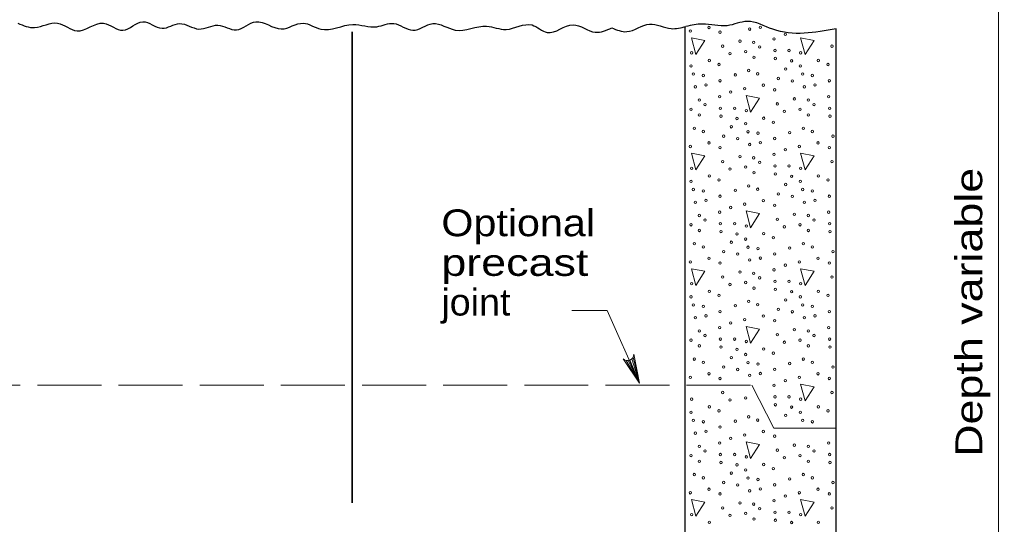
# Model space of a CAD drawing. Extents: x 1083.1 to 1117.1, y 697.4 to 719.4.
# Drawn here: x 1087.12 to 1092.81, y 707.6 to 710.54 of the extents above; entities that cross this region are included whole.
import ezdxf

# ---------------------------------------------------------------- set-up
doc = ezdxf.new("R2010")
doc.units = 0
doc.header["$LTSCALE"] = 0.062
doc.linetypes.add('LONG_DASHED', pattern=[7.5, 6, -1.5])
doc.layers.add('1', color=7, linetype='Continuous', lineweight=13)

msp = doc.modelspace()

# ---------------------------------------------------------------- linework, layer by layer
at = {"layer": '1'}
for p, q in [((1092.8115, 707.72683), (1092.8115, 711.52217)), ((1091.73883, 710.417), (1091.66092, 710.43225)), ((1090.68642, 708.574), (1090.72433, 708.42275)), ((1090.64575, 708.555), (1090.72433, 708.42275)), ((1090.65742, 708.55425), (1090.72433, 708.42275)), ((1090.668, 708.557), (1090.72433, 708.42275)), ((1090.67958, 708.56475), (1090.72433, 708.42275)), ((1092.8115, 701.31858), (1092.8115, 707.72683))]:
    msp.add_line(p, q, dxfattribs=at)
at = {"layer": '1', "lineweight": 35}
msp.add_line((1089.05217, 710.46625), (1089.05217, 707.72733), dxfattribs=at)
at = {"layer": '1', "lineweight": 25}
for p, q in [((1090.98767, 710.498), (1090.98767, 706.54908)), ((1091.86725, 706.529), (1091.86725, 710.48442))]:
    msp.add_line(p, q, dxfattribs=at)
at = {"layer": '1', "linetype": 'LONG_DASHED'}
for p, q in [((1086.75008, 708.41083), (1091.37633, 708.41083)), ((1091.37633, 708.41083), (1091.50542, 708.16167)), ((1091.50542, 708.16167), (1091.86567, 708.16167))]:
    msp.add_line(p, q, dxfattribs=at)
at = {"layer": '1'}
for points in [[(1091.02658, 710.43225), (1091.05217, 710.33483), (1091.10442, 710.417)], [(1091.34375, 710.09633), (1091.36942, 709.99908), (1091.42158, 710.08125)], [(1091.02658, 709.76058), (1091.05217, 709.66325), (1091.10442, 709.74542)], [(1091.66092, 709.76058), (1091.68658, 709.66325), (1091.73883, 709.74542)], [(1091.34375, 709.42475), (1091.36942, 709.32742), (1091.42158, 709.4095)], [(1091.02658, 709.08892), (1091.05217, 708.99158), (1091.10442, 709.07375)], [(1091.66092, 709.08892), (1091.68658, 708.99158), (1091.73883, 709.07375)], [(1091.34375, 708.75308), (1091.36942, 708.65575), (1091.42158, 708.73792)], [(1091.66092, 708.41725), (1091.68658, 708.31992), (1091.73883, 708.40208)], [(1091.34375, 708.08142), (1091.36942, 707.98408), (1091.42158, 708.06625)], [(1091.02658, 707.74567), (1091.05217, 707.64825), (1091.10442, 707.73042)], [(1091.66092, 707.74567), (1091.68658, 707.64825), (1091.73883, 707.73042)]]:
    msp.add_lwpolyline(points, close=True, dxfattribs=at)
for points in [[(1091.66092, 710.43225), (1091.68658, 710.33483), (1091.73883, 710.417)], [(1090.72433, 708.42275), (1090.53533, 708.84483), (1090.3305, 708.84483)], [(1090.69025, 708.59092), (1090.72433, 708.42275), (1090.62817, 708.56492)]]:
    msp.add_lwpolyline(points, dxfattribs=at)
msp.add_arc((1090.65393, 708.59041), 0.03631, 224.86313, 0.68926, dxfattribs=at)
for centre in [(1091.01889, 710.47171), (1091.12764, 710.49259), (1091.19277, 710.46539), (1091.36517, 710.48291), (1091.42686, 710.49382), (1091.57188, 710.45268), (1091.30754, 710.41283), (1091.38837, 710.40584), (1091.50685, 710.42548), (1091.02745, 710.34477), (1091.2082, 710.38378), (1091.24934, 710.34024), (1091.34095, 710.35205), (1091.42205, 710.37925), (1091.51198, 710.35837), (1091.59424, 710.35837), (1091.66186, 710.34477), (1091.84261, 710.38378), (1091.12938, 710.30033), (1091.18589, 710.27677), (1091.38922, 710.31908), (1091.51452, 710.31214), (1091.60793, 710.29854), (1091.76378, 710.30033), (1091.8203, 710.27677), (1091.02402, 710.2686), (1091.03776, 710.22147), (1091.28042, 710.21666), (1091.35925, 710.24201), (1091.41148, 710.22298), (1091.57447, 710.25046), (1091.65842, 710.2686), (1091.67216, 710.22147), (1091.09512, 710.21324), (1091.19277, 710.1824), (1091.53138, 710.19578), (1091.61216, 710.18156), (1091.72952, 710.21324), (1091.82717, 710.1824), (1091.04797, 710.14708), (1091.10966, 710.158), (1091.25467, 710.11686), (1091.33609, 710.13589), (1091.44484, 710.15677), (1091.50997, 710.12957), (1091.68237, 710.14708), (1091.74406, 710.158), (1091.07117, 710.07001), (1091.18965, 710.08966), (1091.52541, 710.04796), (1091.62474, 710.07701), (1091.70558, 710.07001), (1091.82405, 710.08966), (1091.02375, 710.01622), (1091.10485, 710.04343), (1091.19478, 710.02255), (1091.27704, 710.02255), (1091.34465, 710.00895), (1091.56654, 710.00441), (1091.65815, 710.01622), (1091.73925, 710.04343), (1091.82918, 710.02255), (1091.07202, 709.98326), (1091.19731, 709.97632), (1091.29073, 709.96272), (1091.34122, 709.93277), (1091.44658, 709.96451), (1091.5031, 709.94094), (1091.70642, 709.98326), (1091.83172, 709.97632), (1091.04204, 709.90619), (1091.09428, 709.88716), (1091.25727, 709.91464), (1091.35496, 709.88564), (1091.41232, 709.87742), (1091.59762, 709.88083), (1091.67645, 709.90619), (1091.72868, 709.88716), (1091.12764, 709.82094), (1091.21418, 709.85995), (1091.29496, 709.84574), (1091.42686, 709.82217), (1091.50997, 709.84658), (1091.76204, 709.82094), (1091.84858, 709.85995), (1091.01889, 709.80007), (1091.19277, 709.79374), (1091.36517, 709.81126), (1091.57188, 709.78104), (1091.65329, 709.80007), (1091.82717, 709.79374), (1091.2082, 709.71214), (1091.30754, 709.74118), (1091.38837, 709.73419), (1091.42205, 709.7076), (1091.50685, 709.75383), (1091.84261, 709.71214), (1091.02745, 709.67312), (1091.24934, 709.66859), (1091.34095, 709.6804), (1091.38922, 709.64743), (1091.51198, 709.68672), (1091.59424, 709.68672), (1091.66186, 709.67312), (1091.02402, 709.59695), (1091.12938, 709.62868), (1091.18589, 709.60512), (1091.51452, 709.64049), (1091.60793, 709.62689), (1091.65842, 709.59695), (1091.76378, 709.62868), (1091.8203, 709.60512), (1091.03776, 709.54982), (1091.09512, 709.54159), (1091.28042, 709.54501), (1091.35925, 709.57036), (1091.41148, 709.55133), (1091.57447, 709.57881), (1091.67216, 709.54982), (1091.72952, 709.54159), (1091.10966, 709.48635), (1091.19277, 709.51075), (1091.44484, 709.48512), (1091.53138, 709.52413), (1091.61216, 709.50991), (1091.74406, 709.48635), (1091.82717, 709.51075), (1091.04797, 709.47543), (1091.25467, 709.44521), (1091.33609, 709.46424), (1091.50997, 709.45792), (1091.68237, 709.47543), (1091.07117, 709.39836), (1091.10485, 709.37178), (1091.18965, 709.41801), (1091.52541, 709.37631), (1091.62474, 709.40536), (1091.70558, 709.39836), (1091.73925, 709.37178), (1091.82405, 709.41801), (1091.02375, 709.34458), (1091.07202, 709.31161), (1091.19478, 709.3509), (1091.27704, 709.3509), (1091.34465, 709.3373), (1091.56654, 709.33277), (1091.65815, 709.34458), (1091.70642, 709.31161), (1091.82918, 709.3509), (1091.19731, 709.30467), (1091.29073, 709.29107), (1091.34122, 709.26112), (1091.44658, 709.29286), (1091.5031, 709.26929), (1091.83172, 709.30467), (1091.04204, 709.23454), (1091.09428, 709.21551), (1091.25727, 709.24299), (1091.35496, 709.214), (1091.41232, 709.20577), (1091.59762, 709.20918), (1091.67645, 709.23454), (1091.72868, 709.21551), (1091.12764, 709.14929), (1091.21418, 709.1883), (1091.29496, 709.17409), (1091.36517, 709.13961), (1091.42686, 709.15052), (1091.50997, 709.17493), (1091.76204, 709.14929), (1091.84858, 709.1883), (1091.01889, 709.12842), (1091.19277, 709.12209), (1091.50685, 709.08218), (1091.57188, 709.10939), (1091.65329, 709.12842), (1091.82717, 709.12209), (1091.2082, 709.04049), (1091.30754, 709.06953), (1091.38837, 709.06254), (1091.42205, 709.03595), (1091.84261, 709.04049), (1091.02745, 709.00147), (1091.24934, 708.99694), (1091.34095, 709.00875), (1091.38922, 708.97578), (1091.51198, 709.01508), (1091.51452, 708.96884), (1091.59424, 709.01508), (1091.66186, 709.00147), (1091.02402, 708.9253), (1091.12938, 708.95703), (1091.18589, 708.93347), (1091.57447, 708.90716), (1091.60793, 708.95524), (1091.65842, 708.9253), (1091.76378, 708.95703), (1091.8203, 708.93347), (1091.03776, 708.87817), (1091.09512, 708.86994), (1091.28042, 708.87336), (1091.35925, 708.89871), (1091.41148, 708.87968), (1091.53138, 708.85248), (1091.67216, 708.87817), (1091.72952, 708.86994), (1091.04797, 708.80379), (1091.10966, 708.8147), (1091.19277, 708.8391), (1091.33609, 708.79259), (1091.44484, 708.81347), (1091.61216, 708.83826), (1091.68237, 708.80379), (1091.74406, 708.8147), (1091.82717, 708.8391), (1091.18965, 708.74636), (1091.25467, 708.77356), (1091.50997, 708.78627), (1091.82405, 708.74636), (1091.07117, 708.72671), (1091.10485, 708.70013), (1091.19478, 708.67925), (1091.27704, 708.67925), (1091.52541, 708.70466), (1091.62474, 708.73371), (1091.70558, 708.72671), (1091.73925, 708.70013), (1091.82918, 708.67925), (1091.02375, 708.67293), (1091.07202, 708.63996), (1091.19731, 708.63302), (1091.34465, 708.66565), (1091.56654, 708.66112), (1091.65815, 708.67293), (1091.70642, 708.63996), (1091.83172, 708.63302), (1091.25727, 708.57134), (1091.29073, 708.61942), (1091.34122, 708.58947), (1091.44658, 708.62121), (1091.5031, 708.59765), (1091.04204, 708.56289), (1091.09428, 708.54386), (1091.21418, 708.51666), (1091.35496, 708.54235), (1091.41232, 708.53412), (1091.59762, 708.53753), (1091.67645, 708.56289), (1091.72868, 708.54386), (1091.84858, 708.51666), (1091.01889, 708.45677), (1091.12764, 708.47764), (1091.29496, 708.50244), (1091.36517, 708.46796), (1091.42686, 708.47888), (1091.50997, 708.50328), (1091.65329, 708.45677), (1091.76204, 708.47764), (1091.19277, 708.45044), (1091.50685, 708.41054), (1091.57188, 708.43774), (1091.82717, 708.45044), (1091.2082, 708.36884), (1091.34095, 708.3371), (1091.51198, 708.34343), (1091.59424, 708.34343), (1091.84261, 708.36884), (1091.02745, 708.32983), (1091.12938, 708.28538), (1091.24934, 708.32529), (1091.51452, 708.29719), (1091.60793, 708.28359), (1091.66186, 708.32983), (1091.76378, 708.28538), (1091.02402, 708.25365), (1091.18589, 708.26182), (1091.35925, 708.22706), (1091.57447, 708.23551), (1091.65842, 708.25365), (1091.8203, 708.26182), (1091.03776, 708.20652), (1091.09512, 708.19829), (1091.19277, 708.16745), (1091.28042, 708.20171), (1091.41148, 708.20803), (1091.67216, 708.20652), (1091.72952, 708.19829), (1091.04797, 708.13214), (1091.10966, 708.14305), (1091.33609, 708.12094), (1091.44484, 708.14182), (1091.50997, 708.11462), (1091.07117, 708.05506), (1091.18965, 708.07471), (1091.25467, 708.10191), (1091.62474, 708.06206), (1091.70558, 708.05506), (1091.82405, 708.07471), (1091.02375, 708.00128), (1091.10485, 708.02848), (1091.19478, 708.0076), (1091.27704, 708.0076), (1091.52541, 708.03301), (1091.65815, 708.00128), (1091.73925, 708.02848), (1091.82918, 708.0076), (1091.07202, 707.96831), (1091.19731, 707.96137), (1091.29073, 707.94777), (1091.34465, 707.994), (1091.44658, 707.94956), (1091.56654, 707.98947), (1091.70642, 707.96831), (1091.83172, 707.96137), (1091.04204, 707.89124), (1091.25727, 707.89969), (1091.34122, 707.91782), (1091.5031, 707.926), (1091.67645, 707.89124), (1091.09428, 707.87221), (1091.21418, 707.84501), (1091.29496, 707.83079), (1091.35496, 707.8707), (1091.41232, 707.86247), (1091.50997, 707.83163), (1091.59762, 707.86588), (1091.72868, 707.87221), (1091.84858, 707.84501), (1091.01889, 707.78512), (1091.12764, 707.80599), (1091.19277, 707.77879), (1091.36517, 707.79631), (1091.42686, 707.80723), (1091.65329, 707.78512), (1091.76204, 707.80599), (1091.82717, 707.77879), (1091.30754, 707.72624), (1091.38837, 707.71924), (1091.50685, 707.73889), (1091.57188, 707.76609), (1091.02745, 707.65818), (1091.2082, 707.69719), (1091.34095, 707.66545), (1091.42205, 707.69265), (1091.51198, 707.67178), (1091.59424, 707.67178), (1091.66186, 707.65818), (1091.84261, 707.69719), (1091.12938, 707.61374), (1091.24934, 707.65364), (1091.38922, 707.63249), (1091.51452, 707.62555), (1091.60793, 707.61194), (1091.76378, 707.61374)]:
    msp.add_ellipse(centre, major_axis=(0, 0.00718), ratio=0.944544, dxfattribs=at)
at = {"layer": '1', "lineweight": 25}
for points in [[(1087.10817, 710.517), (1087.20492, 710.49192), (1087.33917, 710.51783), (1087.45192, 710.47258), (1087.60658, 710.51717), (1087.71933, 710.47667), (1087.834, 710.52592), (1087.94675, 710.4875), (1088.04833, 710.51525), (1088.161, 710.48358), (1088.272, 710.5055), (1088.37908, 710.47867), (1088.49192, 710.526), (1088.64008, 710.48383), (1088.76775, 710.5175), (1088.86925, 710.48283), (1089.05667, 710.51), (1089.1955, 710.497), (1089.29433, 710.516), (1089.40508, 710.4765), (1089.52167, 710.51508), (1089.65117, 710.47767), (1089.83475, 710.49992), (1089.9475, 710.48092), (1090.0985, 710.50692), (1090.187, 710.4635), (1090.33708, 710.50808), (1090.46658, 710.46475), (1090.563, 710.49058)], [(1090.56233, 710.49058), (1090.64958, 710.46817), (1090.78283, 710.51167), (1090.90767, 710.48592), (1090.99375, 710.49833)], [(1091.86725, 710.48442), (1091.49942, 710.48175), (1091.35033, 710.52792), (1091.23383, 710.503), (1091.08942, 710.51208), (1090.99375, 710.49833)]]:
    msp.add_spline(points, degree=3, dxfattribs=at)

# ---------------------------------------------------------------- texts
at = {"layer": '1', "width": 1.25}
msp.add_text('Depth variable', height=0.156, rotation=90, dxfattribs=at).set_placement((1092.71742, 707.99442))
at = {"layer": '1'}
for s, width, p in [('Optional', 1.15, (1089.57125, 709.27792)), ('precast', 1.25, (1089.57125, 709.04717)), ('joint', 1.05, (1089.57125, 708.81642))]:
    msp.add_text(s, height=0.156, dxfattribs=dict(at, width=width)).set_placement(p)

doc.saveas('drawing.dxf')
